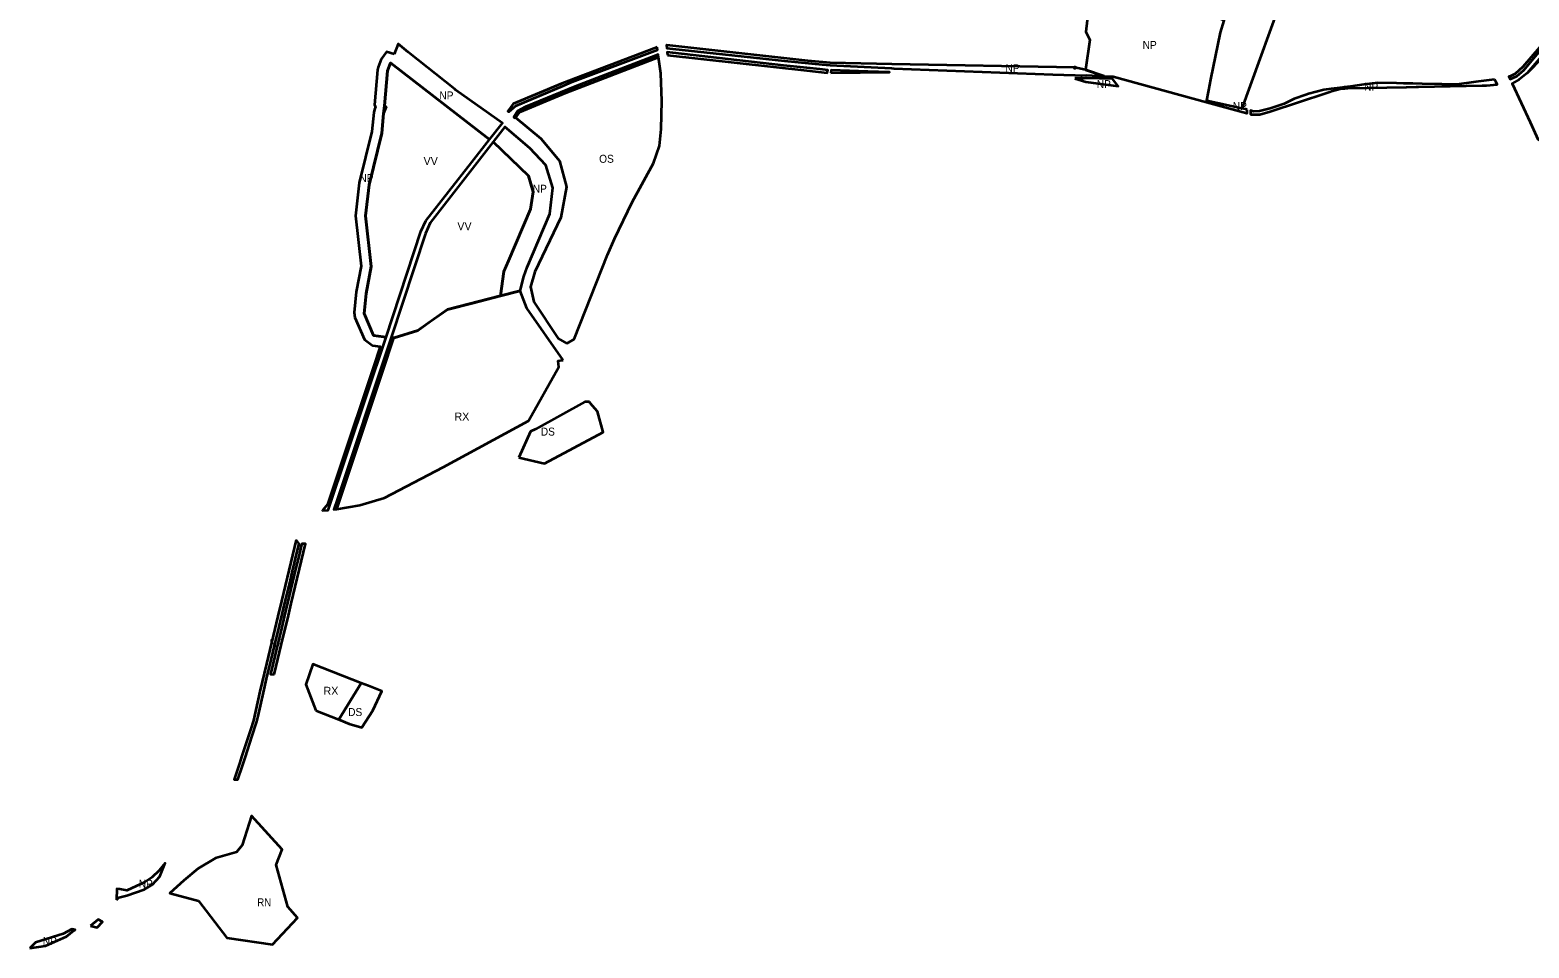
# Model space of a CAD drawing. Extents: x -650276 to -642489, y -1074311 to -1066720.
# Drawn here: x -648979 to -646730, y -1074311 to -1072933 of the extents above; entities that cross this region are included whole.
import ezdxf

# ---------------------------------------------------------------- set-up
doc = ezdxf.new("R2010")
doc.units = 0
doc.header["$LTSCALE"] = 4.8
doc.header["$PDMODE"] = 32
doc.header["$PDSIZE"] = 2.4
for name, color, linetype, lineweight in [('24', 7, 'Continuous', 35), ('42', 7, 'Continuous', 35), ('45', 7, 'Continuous', 35), ('48', 7, 'Continuous', 35), ('5', 7, 'Continuous', 35), ('54', 7, 'Continuous', 35), ('7', 7, 'Continuous', 35), ('9', 7, 'Continuous', 35)]:
    doc.layers.add(name, color=color, linetype=linetype, lineweight=lineweight)
doc.layers.add('62', color=7, linetype='Continuous')

msp = doc.modelspace()

# ---------------------------------------------------------------- linework, layer by layer
at = {"layer": '24'}
msp.add_line((-648245.341, -1073575.152), (-648207, -1073584), dxfattribs=at)
for points in [[(-648139.56, -1073491.4), (-648146.4, -1073491.55), (-648220.42, -1073532.43), (-648227.63, -1073535.89), (-648245.341, -1073575.152)], [(-648207, -1073584), (-648119, -1073537), (-648127.31, -1073505.75), (-648138.41, -1073493.62), (-648139.56, -1073491.4)]]:
    msp.add_lwpolyline(points, dxfattribs=at)
msp.add_lwpolyline([(-648515.333, -1073968.584), (-648499.84, -1073974.76), (-648480.86, -1073980.25), (-648464.44, -1073954.69), (-648451.05, -1073925.87), (-648471, -1073918), (-648481.749, -1073913.76)], close=True, dxfattribs=at)
at = {"layer": '42'}
msp.add_lwpolyline([(-646668.53, -1072935.52), (-646680.07, -1072945.74), (-646710.3, -1072975.31), (-646732.95, -1072998.07), (-646744.92, -1073007.46), (-646755.58, -1073013.43), (-646728.25, -1073071.54), (-646719.09, -1073092.43), (-646716.98, -1073097.26), (-646709.88, -1073101.87), (-646700.42, -1073100.42), (-646650.54, -1073072.96), (-646631.82, -1073062.65), (-646629.15, -1073059.18), (-646626.91, -1073048.17), (-646626.55, -1073041.48), (-646625.01, -1073016.38)], close=True, dxfattribs=at)
at = {"layer": '45'}
for points in [[(-648463.25, -1073392.125), (-648444.523, -1073394.235), (-648392.43, -1073235.98), (-648384.6, -1073219.54), (-648315.955, -1073131.889), (-648289.148, -1073097.66), (-648437.643, -1072982.601), (-648442.187, -1072994.5), (-648447.043, -1073046.967), (-648444.11, -1073048.69), (-648448.1, -1073058.393)], [(-648448.1, -1073058.393), (-648450.875, -1073088.375), (-648469.875, -1073165.5), (-648475.437, -1073212.375), (-648466.687, -1073288.25), (-648474.5, -1073328.75), (-648477.562, -1073358.875), (-648463.25, -1073392.125)], [(-648272.642, -1073332.558), (-648268, -1073296), (-648261, -1073280), (-648228, -1073202), (-648224, -1073176), (-648231, -1073152), (-648283.884, -1073101.15), (-648311.798, -1073137.127), (-648378.17, -1073222.67), (-648385.09, -1073238.58), (-648436.857, -1073395.099)], [(-648397.062, -1073384.375), (-648378.125, -1073370.875), (-648352.312, -1073353), (-648314.687, -1073343.25), (-648272.642, -1073332.558)], [(-648436.857, -1073395.099), (-648432.187, -1073395.625), (-648397.062, -1073384.375)]]:
    msp.add_lwpolyline(points, dxfattribs=at)
at = {"layer": '48'}
msp.add_line((-646779.55, -1073011.68), (-646781.703, -1073007.452), dxfattribs=at)
for points in [[(-646642.438, -1072844.29), (-646642.939, -1072845.68), (-646643.574, -1072869.57), (-646650.798, -1072879.828), (-646653.846, -1072889.44), (-646692.432, -1072934.135), (-646739.241, -1072988.798), (-646751.061, -1072999.106), (-646758.883, -1073002.885), (-646760.416, -1073003.25), (-646758.44, -1073007.19), (-646748.51, -1073002.74), (-646737.7, -1072993.52), (-646717.7, -1072969.5), (-646689.13, -1072936.62), (-646644.12, -1072884.84), (-646640.92, -1072879.6), (-646637.92, -1072870.91), (-646637.52, -1072867.43), (-646631.85, -1072818.45), (-646631.08, -1072812.68), (-646640.313, -1072838.394), (-646642.404, -1072844.195), (-646642.39, -1072844.2)], [(-647293.317, -1072873.549), (-647293.351, -1072873.533), (-647331.82, -1072854.49), (-647375.92, -1072833.99), (-647387.64, -1072868.69), (-647392.96, -1072918.277), (-647394.87, -1072936.08), (-647388.62, -1072948.03), (-647395.47, -1072993.25), (-647367.45, -1073002.47), (-647353.78, -1073003.1), (-647213.99, -1073041.449), (-647210.396, -1073023.593), (-647207.176, -1073007.598), (-647192.93, -1072936.82), (-647187.445, -1072918.804), (-647192.718, -1072916.582), (-647282.31, -1072878.82), (-647284.75, -1072877.79)], [(-648037.595, -1072959.123), (-648038.877, -1072959.418), (-648180.651, -1073013.629), (-648253.635, -1073044.348), (-648261.902, -1073054.939), (-648260.27, -1073056.17), (-648250.04, -1073047.08), (-648178.89, -1073017.03), (-648165.13, -1073011.22), (-648037.17, -1072963.24)], [(-648251.027, -1073065.418), (-648250.491, -1073064.698), (-648244.214, -1073056.657), (-648175.061, -1073027.551), (-648035.592, -1072974.222), (-648036.2, -1072969.98), (-648040.06, -1072971.47), (-648161.07, -1073017.9), (-648235.47, -1073048.4), (-648247.16, -1073055.34), (-648252.64, -1073064.13)], [(-648022.279, -1072971.102), (-647813.331, -1072994.317), (-647782.72, -1072997.397), (-647781.65, -1072993.53), (-647793.59, -1072992.29), (-647813.2, -1072990.26), (-647848.15, -1072986.63), (-648014.58, -1072967.51), (-648022.74, -1072966.57)], [(-647777.337, -1072997.711), (-647689.11, -1072996.49), (-647721.83, -1072995.45), (-647776.77, -1072993.69)], [(-647411.34, -1073005.89), (-647394.782, -1073011.002), (-647346.22, -1073017.52), (-647354.76, -1073006.65), (-647394.59, -1073005.58), (-647395.08, -1073005.64), (-647397.74, -1073005.95), (-647400.27, -1073006.24), (-647400.76, -1073006.29), (-647403.05, -1073006.2)], [(-647152.621, -1073052.925), (-647154.999, -1073052.287), (-647161.068, -1073050.946), (-647161.068, -1073050.946), (-647161.068, -1073050.946), (-647213.218, -1073039.42), (-647213.562, -1073039.322), (-647213.99, -1073041.449), (-647153.44, -1073058.06), (-647152.96, -1073058.19)], [(-647006.715, -1073019.236), (-647009.402, -1073019.582), (-647026.763, -1073021.811), (-647037.971, -1073023.24), (-647060.677, -1073029.351), (-647064.784, -1073030.747), (-647082.267, -1073036.684), (-647097.466, -1073044.268), (-647118.513, -1073051.327), (-647134.596, -1073054.974), (-647143.312, -1073055.421), (-647147.85, -1073054.204), (-647147.91, -1073059.64), (-647147.43, -1073059.78), (-647147.17, -1073059.97), (-647134.03, -1073059.94), (-647118.27, -1073055.88), (-647033.44, -1073027.43), (-647028.91, -1073025.91), (-647026.54, -1073025.11), (-647013.4, -1073021.42), (-647006.15, -1073020.99)], [(-648231, -1073152), (-648224, -1073176), (-648228, -1073202), (-648261, -1073280), (-648268, -1073296), (-648272.642, -1073332.558), (-648243.08, -1073325.04), (-648237.98, -1073303.4), (-648232.64, -1073289.31), (-648198.7, -1073209.08), (-648194.2, -1073170.13), (-648205.04, -1073136.07), (-648228.91, -1073110.54), (-648266.38, -1073078.59), (-648283.884, -1073101.15)], [(-648518.867, -1073652.836), (-648499.399, -1073594.679), (-648449.599, -1073445.278), (-648433.206, -1073395.51), (-648436.857, -1073395.099), (-648440.74, -1073406.84), (-648517.47, -1073637.26), (-648522.79, -1073653.23), (-648518.867, -1073652.836)], [(-648612.186, -1073900.905), (-648609.231, -1073888.415), (-648599.275, -1073846.445), (-648592.044, -1073816.692), (-648586.715, -1073794.059), (-648565.224, -1073704.393), (-648565.224, -1073704.393), (-648570.99, -1073704.56), (-648571.72, -1073707.63), (-648573.46, -1073714.88), (-648576.05, -1073725.82), (-648579.57, -1073740.47), (-648592.17, -1073793.18), (-648597.23, -1073814.32), (-648601.98, -1073834.2), (-648606.83, -1073854.48), (-648613.78, -1073883.59), (-648617.72, -1073900.06)], [(-648848.696, -1074238.993), (-648845.424, -1074235.305), (-648833.449, -1074232.685), (-648807.065, -1074223.704), (-648794.902, -1074216.219), (-648783.863, -1074204.056), (-648775.93, -1074183.91), (-648784.8, -1074195.26), (-648795.65, -1074205.35), (-648806.55, -1074212.62), (-648833.11, -1074225.2), (-648844.05, -1074223.24), (-648848.28, -1074222.49)], [(-648887.619, -1074278.134), (-648877.799, -1074280.64), (-648870.041, -1074271.932), (-648876.21, -1074268.73)], [(-648978.575, -1074311.426), (-648955.265, -1074308.325), (-648923.698, -1074294.313), (-648912.63, -1074284.912), (-648910.988, -1074284.211), (-648915.73, -1074283.08), (-648929.03, -1074290.14), (-648970.3, -1074302.9)]]:
    msp.add_lwpolyline(points, close=True, dxfattribs=at)
for points in [[(-646684.36, -1072941.43), (-646732.95, -1072998.07), (-646710.3, -1072975.31)], [(-648432.527, -1072969.463), (-648443.591, -1072965.983), (-648451.657, -1072977.25), (-648456.2, -1072989.149), (-648457.123, -1072993.118), (-648461.979, -1073045.585), (-648460.355, -1073048.753), (-648461.973, -1073052.688), (-648463.036, -1073057.011), (-648465.708, -1073085.876), (-648484.661, -1073162.812), (-648490.539, -1073212.35), (-648481.853, -1073287.675), (-648489.355, -1073326.567), (-648492.485, -1073357.358), (-648491.34, -1073364.805), (-648477.028, -1073398.055), (-648464.929, -1073407.031), (-648453.228, -1073408.349), (-648463.838, -1073440.559), (-648513.627, -1073589.927), (-648532.252, -1073645.567), (-648539.599, -1073654.802), (-648531.31, -1073654.08), (-648444.523, -1073394.235), (-648448.434, -1073393.794), (-648463.25, -1073392.125), (-648477.562, -1073358.875), (-648474.5, -1073328.75), (-648466.687, -1073288.25), (-648475.437, -1073212.375), (-648469.875, -1073165.5), (-648450.875, -1073088.375), (-648448.1, -1073058.393), (-648447.043, -1073046.967), (-648442.187, -1072994.5), (-648437.643, -1072982.601)], [(-648437.643, -1072982.601), (-648289.148, -1073097.66), (-648269.78, -1073072.93), (-648339.58, -1073023.82), (-648341.495, -1073022.285), (-648411.09, -1072966.5), (-648426.547, -1072954.108), (-648432.527, -1072969.463)], [(-647685.748, -1072984.544), (-647778.296, -1072982.767), (-647811.752, -1072979.4), (-648023.495, -1072955.875), (-648023.818, -1072955.949), (-648023.37, -1072960.37), (-648014.16, -1072961.36), (-647846.85, -1072979.37), (-647790.52, -1072985.06), (-647778.3, -1072986.29), (-647686.14, -1072990.78)], [(-647686.14, -1072990.78), (-647682.74, -1072990.95), (-647497.35, -1072997.93), (-647444.42, -1072999.87), (-647411.326, -1073001.08)], [(-647411.294, -1072989.813), (-647411.298, -1072989.813), (-647685.748, -1072984.544)], [(-647411.326, -1073001.08), (-647410.791, -1073001.197), (-647410.79, -1073001.1), (-647402.49, -1073001.41), (-647400.55, -1073001.48), (-647394.46, -1073001.23), (-647367.45, -1073002.47), (-647395.47, -1072993.25), (-647411.293, -1072989.813), (-647411.294, -1072989.813)], [(-646918.156, -1073013.511), (-646928.807, -1073013.313), (-646956.919, -1073012.775), (-646978.077, -1073014.931), (-646997.824, -1073018.092), (-647006.715, -1073019.236), (-647006.15, -1073020.99), (-647001.66, -1073020.72), (-646914.54, -1073019)], [(-646781.703, -1073007.452), (-646809.778, -1073011.019), (-646838.25, -1073014.938), (-646861.07, -1073014.672), (-646890.523, -1073014.073), (-646904.131, -1073013.793), (-646914.796, -1073013.573), (-646918.156, -1073013.511)], [(-646914.54, -1073019), (-646913.94, -1073018.99), (-646899.22, -1073018.7), (-646895.76, -1073018.63), (-646800.44, -1073016.74)], [(-646800.44, -1073016.74), (-646793.8, -1073016.61), (-646777.74, -1073015.29), (-646779.55, -1073011.68)], [(-648579.272, -1073698.648), (-648601.309, -1073790.592), (-648606.633, -1073813.202), (-648613.86, -1073842.943), (-648623.827, -1073884.957), (-648633.591, -1073926.228), (-648643.415, -1073969.782), (-648647.944, -1073983.639), (-648660.613, -1074022.822), (-648664.22, -1074034.155)], [(-648659.85, -1074037.72), (-648655.5, -1074024.36), (-648645.7, -1073994.3), (-648638.15, -1073971.13), (-648636.34, -1073963.19), (-648628.21, -1073927.61), (-648623.58, -1073907.34), (-648622.06, -1073901.02), (-648617.77, -1073883.09), (-648616.76, -1073878.91), (-648611.69, -1073857.74), (-648607.72, -1073841.19), (-648607.4, -1073839.84), (-648595.71, -1073791.1), (-648588.06, -1073759.19), (-648584.69, -1073745.15), (-648581.82, -1073733.14), (-648578.69, -1073720.11), (-648574.99, -1073704.67), (-648579.272, -1073698.648)], [(-648664.22, -1074034.155), (-648669.584, -1074051.005), (-648672.336, -1074058.391), (-648672.336, -1074058.391), (-648666.67, -1074058.64), (-648659.85, -1074037.72)]]:
    msp.add_lwpolyline(points, dxfattribs=at)
msp.add_point((-647411.294, -1072989.813), dxfattribs=at)
at = {"layer": '5'}
for points in [[(-648179.07, -1073428.81), (-648233.36, -1073350.68), (-648243.08, -1073325.04), (-648272.642, -1073332.558)], [(-648272.642, -1073332.558), (-648352.312, -1073353), (-648397.062, -1073384.375)], [(-648397.062, -1073384.375), (-648432.187, -1073395.625), (-648433.206, -1073395.51), (-648449.599, -1073445.278)], [(-648447.06, -1073635.39), (-648358.69, -1073589.35), (-648230.81, -1073520.18), (-648185.34, -1073438.91), (-648185.82, -1073435.12), (-648186.46, -1073430.01), (-648183.46, -1073429.52), (-648179.07, -1073428.81)], [(-648449.599, -1073445.278), (-648518.867, -1073652.836), (-648483.58, -1073646.7), (-648447.06, -1073635.39), (-648447.06, -1073635.39)]]:
    msp.add_lwpolyline(points, dxfattribs=at)
msp.add_lwpolyline([(-648549.76, -1073954.86), (-648515.333, -1073968.584), (-648498, -1073940), (-648481.749, -1073913.76), (-648554.42, -1073885.092), (-648564.75, -1073915.91)], close=True, dxfattribs=at)
at = {"layer": '54'}
msp.add_lwpolyline([(-646516, -1072345), (-646685.823, -1072502.987), (-646914.429, -1072678.004), (-647018.969, -1072761.795), (-647092.194, -1072861.614), (-647161.068, -1073050.946)], dxfattribs=at)
at = {"layer": '7'}
msp.add_lwpolyline([(-648725.93, -1074240.58), (-648683.5, -1074296.12), (-648683.5, -1074296.12), (-648614.6, -1074306.17), (-648577.25, -1074266.06), (-648591.67, -1074249.72), (-648609.49, -1074186.61), (-648600.53, -1074163.47), (-648646.42, -1074113.19), (-648660.16, -1074156.75), (-648669.01, -1074167.27), (-648700.45, -1074176.73), (-648726.23, -1074192.02), (-648747.74, -1074210.12), (-648768.94, -1074229.25), (-648725.93, -1074240.58), (-648725.93, -1074240.58)], close=True, dxfattribs=at)
at = {"layer": '9'}
for points in [[(-648030.86, -1073039.71), (-648032.09, -1072998.65), (-648035.592, -1072974.222), (-648175.061, -1073027.551), (-648244.214, -1073056.657), (-648250.491, -1073064.698), (-648212.22, -1073096.39), (-648184.37, -1073129.89)], [(-648101.67, -1073246.63), (-648075.34, -1073191.93), (-648043.29, -1073132.97), (-648034.43, -1073107.07), (-648031.8, -1073082.07), (-648030.86, -1073039.71)], [(-648184.37, -1073129.89), (-648174.03, -1073168.94), (-648182.12, -1073214.56), (-648221.39, -1073296.24), (-648227.75, -1073318.75), (-648223.03, -1073341.59), (-648186.47, -1073396.47), (-648173.38, -1073404.03)], [(-648173.38, -1073404.03), (-648162.55, -1073397.4), (-648112.36, -1073270.87), (-648101.67, -1073246.63)]]:
    msp.add_lwpolyline(points, dxfattribs=at)

# ---------------------------------------------------------------- texts
at = {"layer": '62'}
for s, width, p in [('NP', 0.95, (-647309.627, -1072961.756)), ('NP', 0.95, (-647515.505, -1072996.594)), ('NP', 0.95, (-647378.505, -1073020.594)), ('NP', 0.95, (-646977.505, -1073024.594)), ('NP', 0.95, (-648364.505, -1073037.594)), ('NP', 0.95, (-647174.505, -1073053.594)), ('OS', 0.95, (-648124.882, -1073132.612)), ('NP', 0.95, (-648484.505, -1073161.594)), ('NP', 0.95, (-648224.505, -1073177.594)), ('DS', 0.95, (-648212.386, -1073542.148)), ('NP', 0.95, (-648619.524, -1073859.849)), ('DS', 0.95, (-648501.386, -1073963.148)), ('NP', 0.95, (-648815.524, -1074220.849)), ('RN', 0.9, (-648637.627, -1074248.756)), ('NP', 0.95, (-648959.524, -1074306.849))]:
    msp.add_text(s, height=12, dxfattribs=dict(at, width=width)).set_placement(p)
for s, p in [('VV', (-648388.203, -1073135.952)), ('VV', (-648337.553, -1073233.772)), ('RX', (-648341.882, -1073519.612)), ('RX', (-648538.32, -1073931.277))]:
    msp.add_text(s, height=12, dxfattribs=at).set_placement(p)

doc.saveas('drawing.dxf')
